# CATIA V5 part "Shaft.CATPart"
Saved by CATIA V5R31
Part number: Shaft
Bounding box of the stored display mesh (mm): x -10.997 to 10.997, y 0 to 134, z -10.875 to 10.875
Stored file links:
  D:\PROJECTS\Project 2021\US EDITION\CATIA V5 6R 2021\Resources\Part Files\c14_catia_v5_6r2021_prt\c14-catia-v5-6r2021-figr-14-26 & 27\Part & Asm\Shaft.CATPart
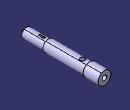
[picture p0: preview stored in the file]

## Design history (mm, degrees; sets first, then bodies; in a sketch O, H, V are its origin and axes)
Body1 (main body)
  Sketch1 on yz-plane, origin (0, 0, 0), H (0, 1, 0), V (0, 0, 1)
    line L1 (0, 0) -> (0, 8)
    line L2 (0, 8) -> (39, 8)
    line L3 (39, 8) -> (39, 9.5)
    line L4 (39, 9.5) -> (109, 9.5)
    line L5 (109, 9.5) -> (109, 11)
    line L6 (109, 11) -> (134, 11)
    line L7 (134, 11) -> (134, 0)
    point P7 (134, 0)
    line L8 (134, 0) -> (0, 0)
    length L1 = 8
    length L8 = 134
    length L7 = 11
    distance L4 L8 = 9.5
    length L6 = 25
    length L4 = 70
    vertical: L1 V, L3 V, L5 V, L7 V
    horizontal: L2 H, L4 H, L6 H, L8 H
    coincidence: P7 H
  Shaft1: profile Sketch1, axis edge of Sketch1, angle 360
  Chamfer1: length 1.5, angle 45, on 1 edge
  Sketch2 on xy-plane, origin (0, 0, 0), H (1, 0, 0), V (0, 1, 0)
    circle A1 centre (0, 97) radius 4.15
    point P1 (0, 97)
    reference projected line E1 (-11, 109) -> (11, 109) from edge of Shaft1
    radius A1 = 4.15
    distance E1 P1 = 12
    coincidence: P1 V
  Pocket1: profile Sketch2, direction (0, 0, -1), length 20, mirrored extent
  Sketch3 on face of Shaft1, origin (0, 134, 0), H (-1, 0, 0), V (0, 0, 1)
    circle A1 centre (0, 0) radius 4.15
    radius A1 = 4.15
  Pocket2: profile Sketch3, direction (0, -1, 0), length 44
  Sketch4 on yz-plane, origin (0, 0, 0), H (0, 1, 0), V (0, 0, 1)
    point P1 (23, 8)
    line L1 (23, 8) -> (33, 8)
    arc A1 centre (28, 12.899) radius 7 from (23, 8) to (33, 8) ccw
    reference projected line E1 (39, -9.5) -> (39, 9.5) from edge of Shaft1
    length L1 = 10
    distance L1 H = 8
    distance P1 E1 = 16
    radius A1 = 7
    horizontal: L1 H
  Pocket3: profile Sketch4, direction (-1, 0, 0), length 1.6, mirrored extent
